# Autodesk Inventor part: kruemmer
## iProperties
Created: 2005-04
Part Number: kruemmer
Material: Stahl (schweißbar)
Document SubType Name: Modeling
Designer: M.Wipf
Manufacturer: Standard
Standards Organization: Custom
Author: M.Wipf
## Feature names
1. Sweeping1
2. Extrusion1
3. Spiegeln1 [Mirror]
